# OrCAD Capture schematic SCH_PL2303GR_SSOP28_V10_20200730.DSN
size Custom; title: PL2303GR SSOP28 reference schematic; rev: 1.0; note: PL2303GR
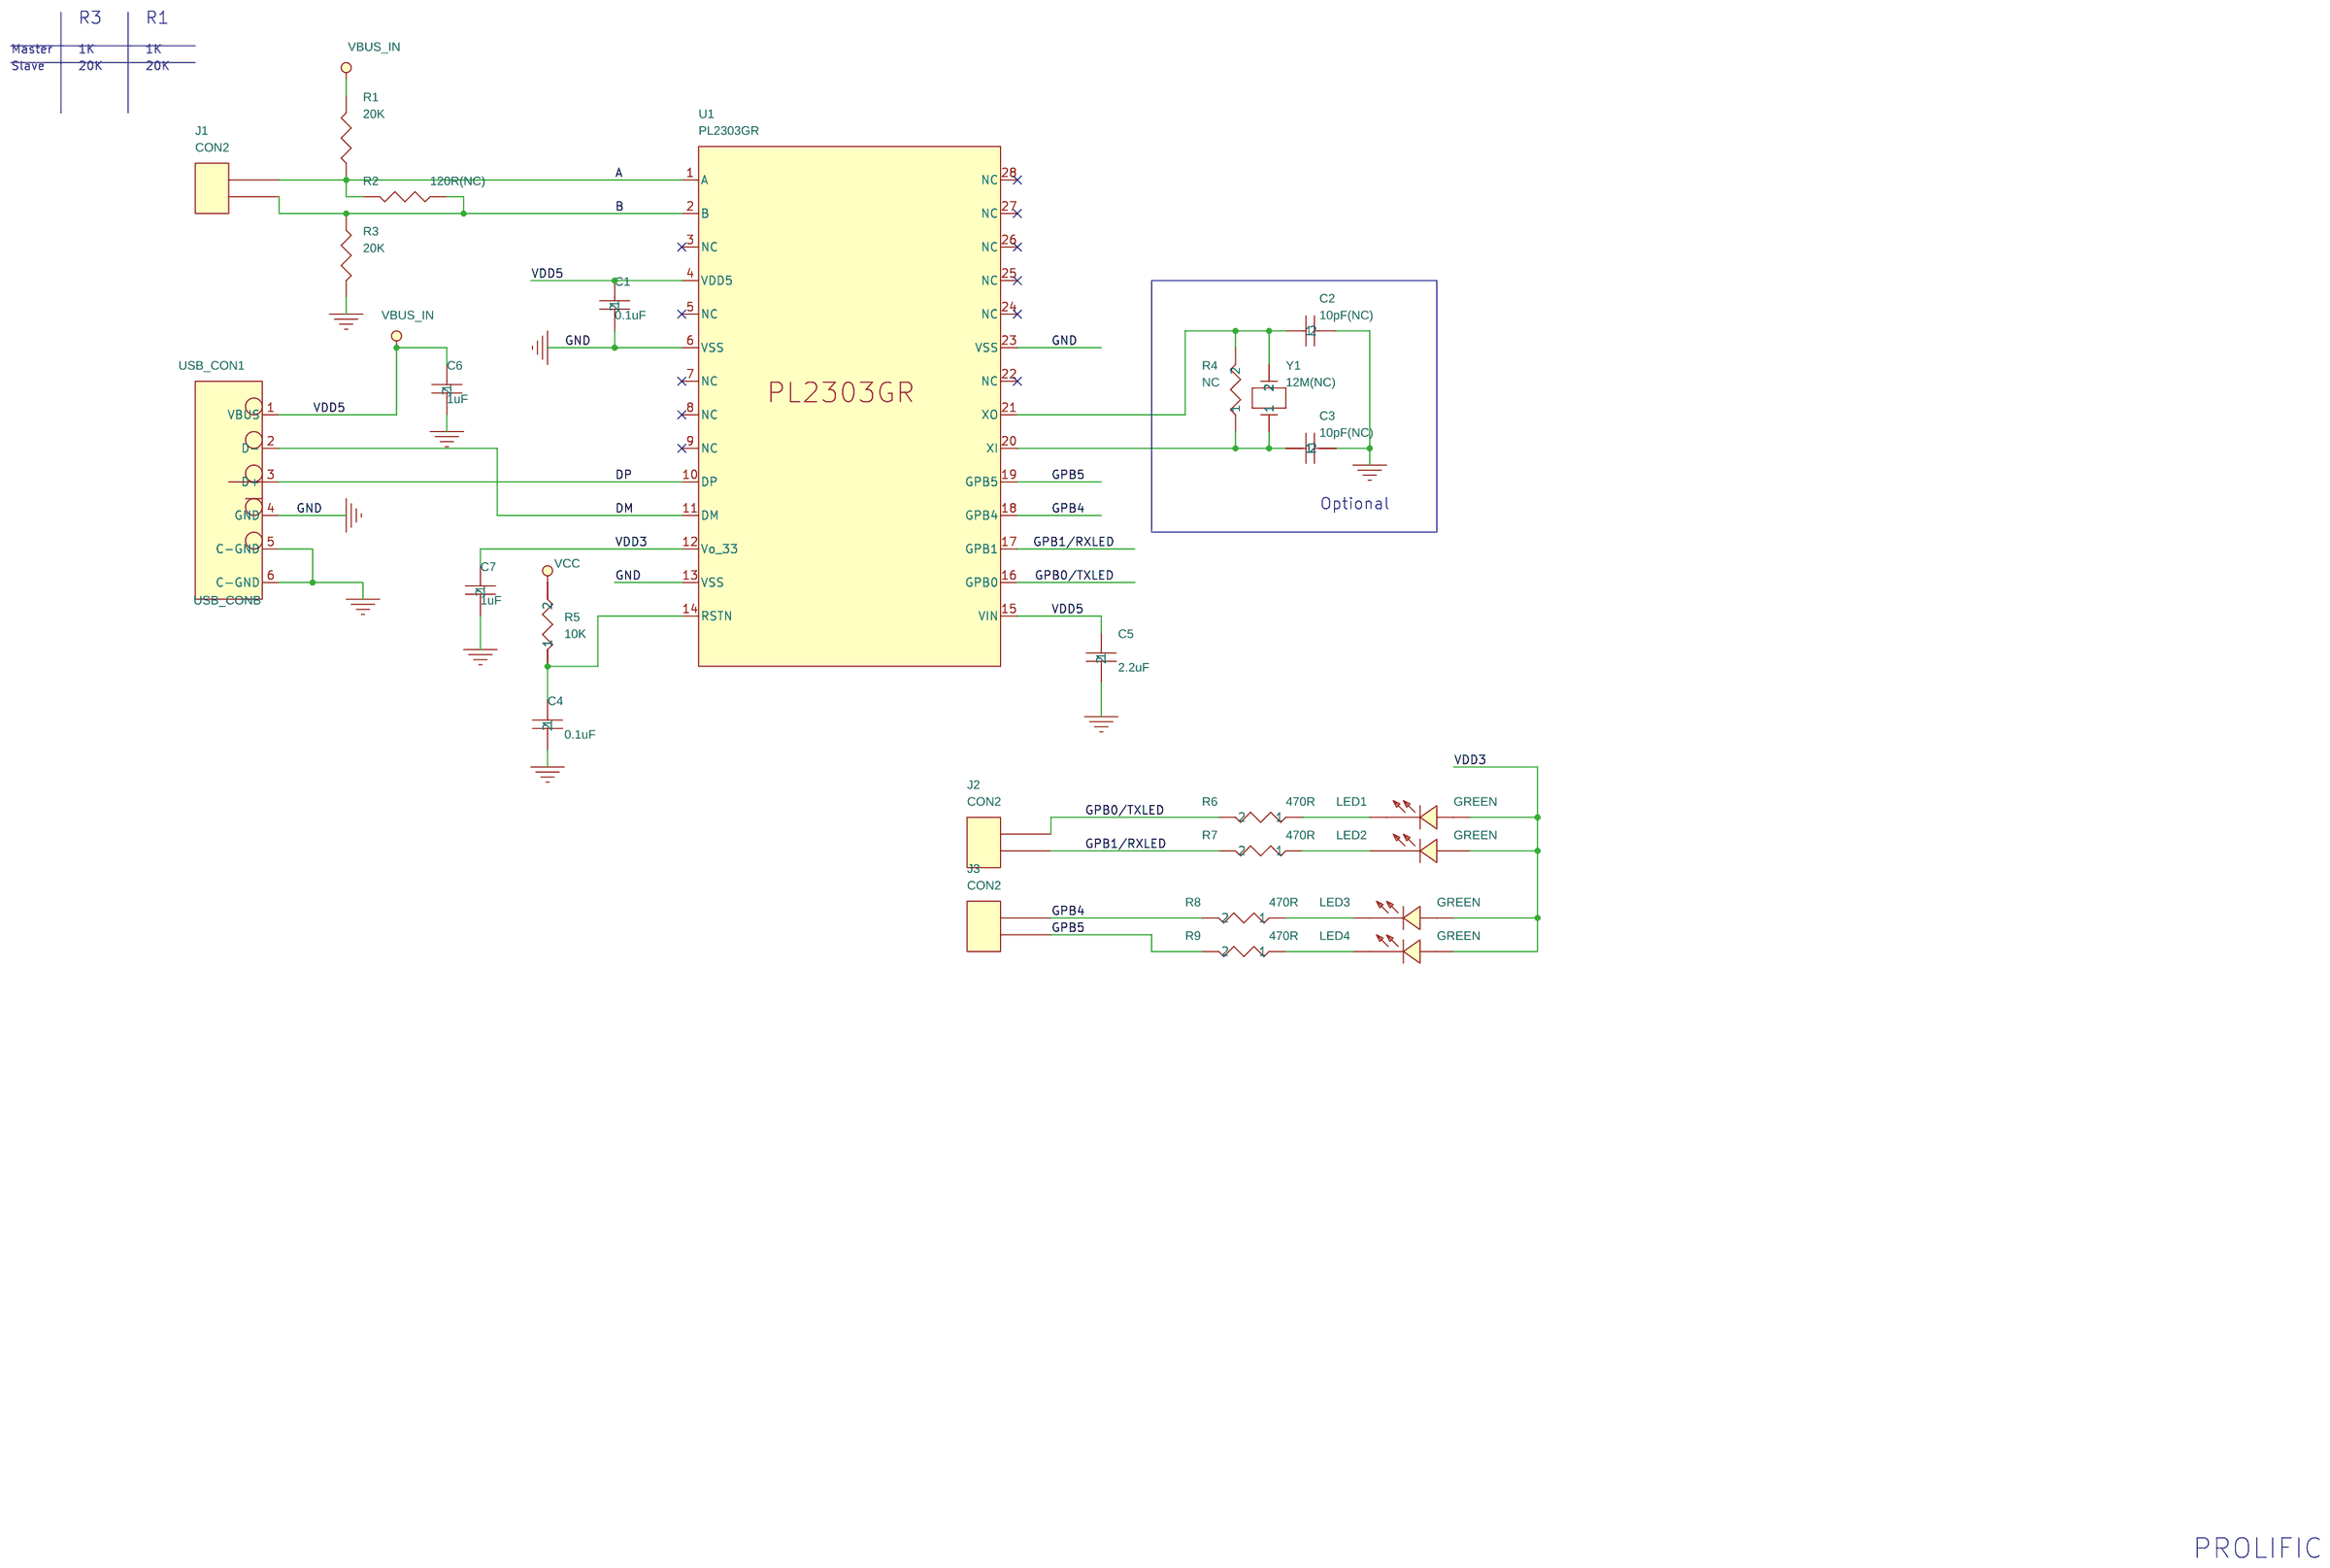
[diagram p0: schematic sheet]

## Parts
C1  0.1uF  [C0603]
C2  10pF(NC)  [C0603]
C3  10pF(NC)  [C0603]
C4  0.1uF  [C0603]
C5  2.2uF  [C0603]
C6  1uF  [C0603]
C7  1uF  [C0603]
J1  CON2  [SIP_2P]
J2  CON2  [SIP_2P]
J3  CON2  [SIP_2P]
LED1  GREEN  [LED-0603]
LED2  GREEN  [LED-0603]
LED3  GREEN  [LED-0603]
LED4  GREEN  [LED-0603]
R1  20K  [R0603]
R2  120R(NC)  [R0603]
R3  20K  [R0603]
R4  NC  [R0603]
R5  10K  [R0603]
R6  470R  [R0603]
R7  470R  [R0603]
R8  470R  [R0603]
R9  470R  [R0603]
U1  PL2303GR  [SSOP28P-209MIL]
USB_CON1  USB_CONB  [CON/USB-BF/D]
Y1  12M(NC)  [XTAL_4.88D]

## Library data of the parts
C1 = CAP_NP_1
C2 = CAP_NP_2
C3 = CAP_NP_6
C4 = CAP_NP
C5 = CAP_NP_3
C6 = CAP_NP_5
C7 = CAP_NP_4
J1-J3 = CON2
LED1-LED4 = LED
R1-R3 = RESISTOR
R4 = R_1
R5 = R
R6 = RES_0603_2
R7 = RES_0603_1
R8 = RES_0603
R9 = RES_0603_3
U1 = PL2303_9
USB_CON1 = USB_CON_1
Y1 = CRYSTAL

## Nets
GND: C1.2 C2.2 C3.2 C4.2 C5.2 C6.2 C7.2 R3.1 U1.6(VSS) U1.13(VSS) U1.23(VSS) USB_CON1.4(GND) USB_CON1.5(C-GND) USB_CON1.6(C-GND)
Vbus_in: C1.1 C5.1 C6.1 R1.1 U1.4(VDD5) U1.15(VIN) USB_CON1.1(VBUS)
VDD3: C7.1 LED1.1(ANODE) LED2.1(ANODE) LED3.1(ANODE) LED4.1(ANODE) R5.2 U1.12(Vo_33)
A: J1.1 R1.2 R2.1 U1.1(A)
B: J1.2 R2.2 R3.2 U1.2(B)
DM: U1.11(DM) USB_CON1.2(D-)
DP: U1.10(DP) USB_CON1.3(D+)
GPB0/TXLED: J2.1 R6.2 U1.16(GPB0)
GPB1/RXLED: J2.2 R7.2 U1.17(GPB1)
GPB4: J3.1 R8.2 U1.18(GPB4)
GPB5: J3.2 R9.2 U1.19(GPB5)
N16832329: C4.1 R5.1 U1.14(RSTN)
N16853134: LED1.2(CATHODE) R6.1
N16853221: LED2.2(CATHODE) R7.1
N16943783: C2.1 R4.2 U1.21(XO) Y1.2
N16943786: C3.1 R4.1 U1.20(XI) Y1.1
N16955727: LED3.2(CATHODE) R8.1
N16955758: LED4.2(CATHODE) R9.1

Not connected (* = marked no-connect by the designer): U1 3(NC)* 5(NC)* 7(NC)* 8(NC)* 9(NC)* 22(NC)* 24(NC)* 25(NC)* 26(NC)* 27(NC)* 28(NC)*

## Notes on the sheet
- R3
- R1
- Master
- 1K
- 1K
- Slave
- 20K
- 20K
- Optional
- PROLIFIC
